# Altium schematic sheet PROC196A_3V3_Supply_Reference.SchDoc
size 431 x 279 mm; Date: Not shown in title block; ApprovedBy: Not shown in title block; CheckedBy: Not shown in title block; Author: Not shown in title block; CompanyName: Not shown in title block; Engineer: Not shown in title block; Organization: Not shown in title block; Address1: Not shown in title block; Address2: Not shown in title block; Address3: Not shown in title block; Address4: Not shown in title block; DocumentNumber: 7; Revision: Use project parameter SCH_Rev; SheetNumber: 7; SheetTotal: 25; PageSetup: Record=PageOptions¦CenterHorizontal=True¦CenterVertical=True¦PrintScale=1.00¦XCorrection=1.00¦YCorrection=1.00¦PrintKind=0¦BorderSize=5000000¦LeftOffset=0¦BottomOffset=0¦Orientation=2¦PaperLength=1000¦PaperWidth=1000¦Scale=100¦PaperSource=15¦PrintQuality=600¦MediaType=1¦DitherType=10¦PaperKind=Letter¦PrintScaleMode=1
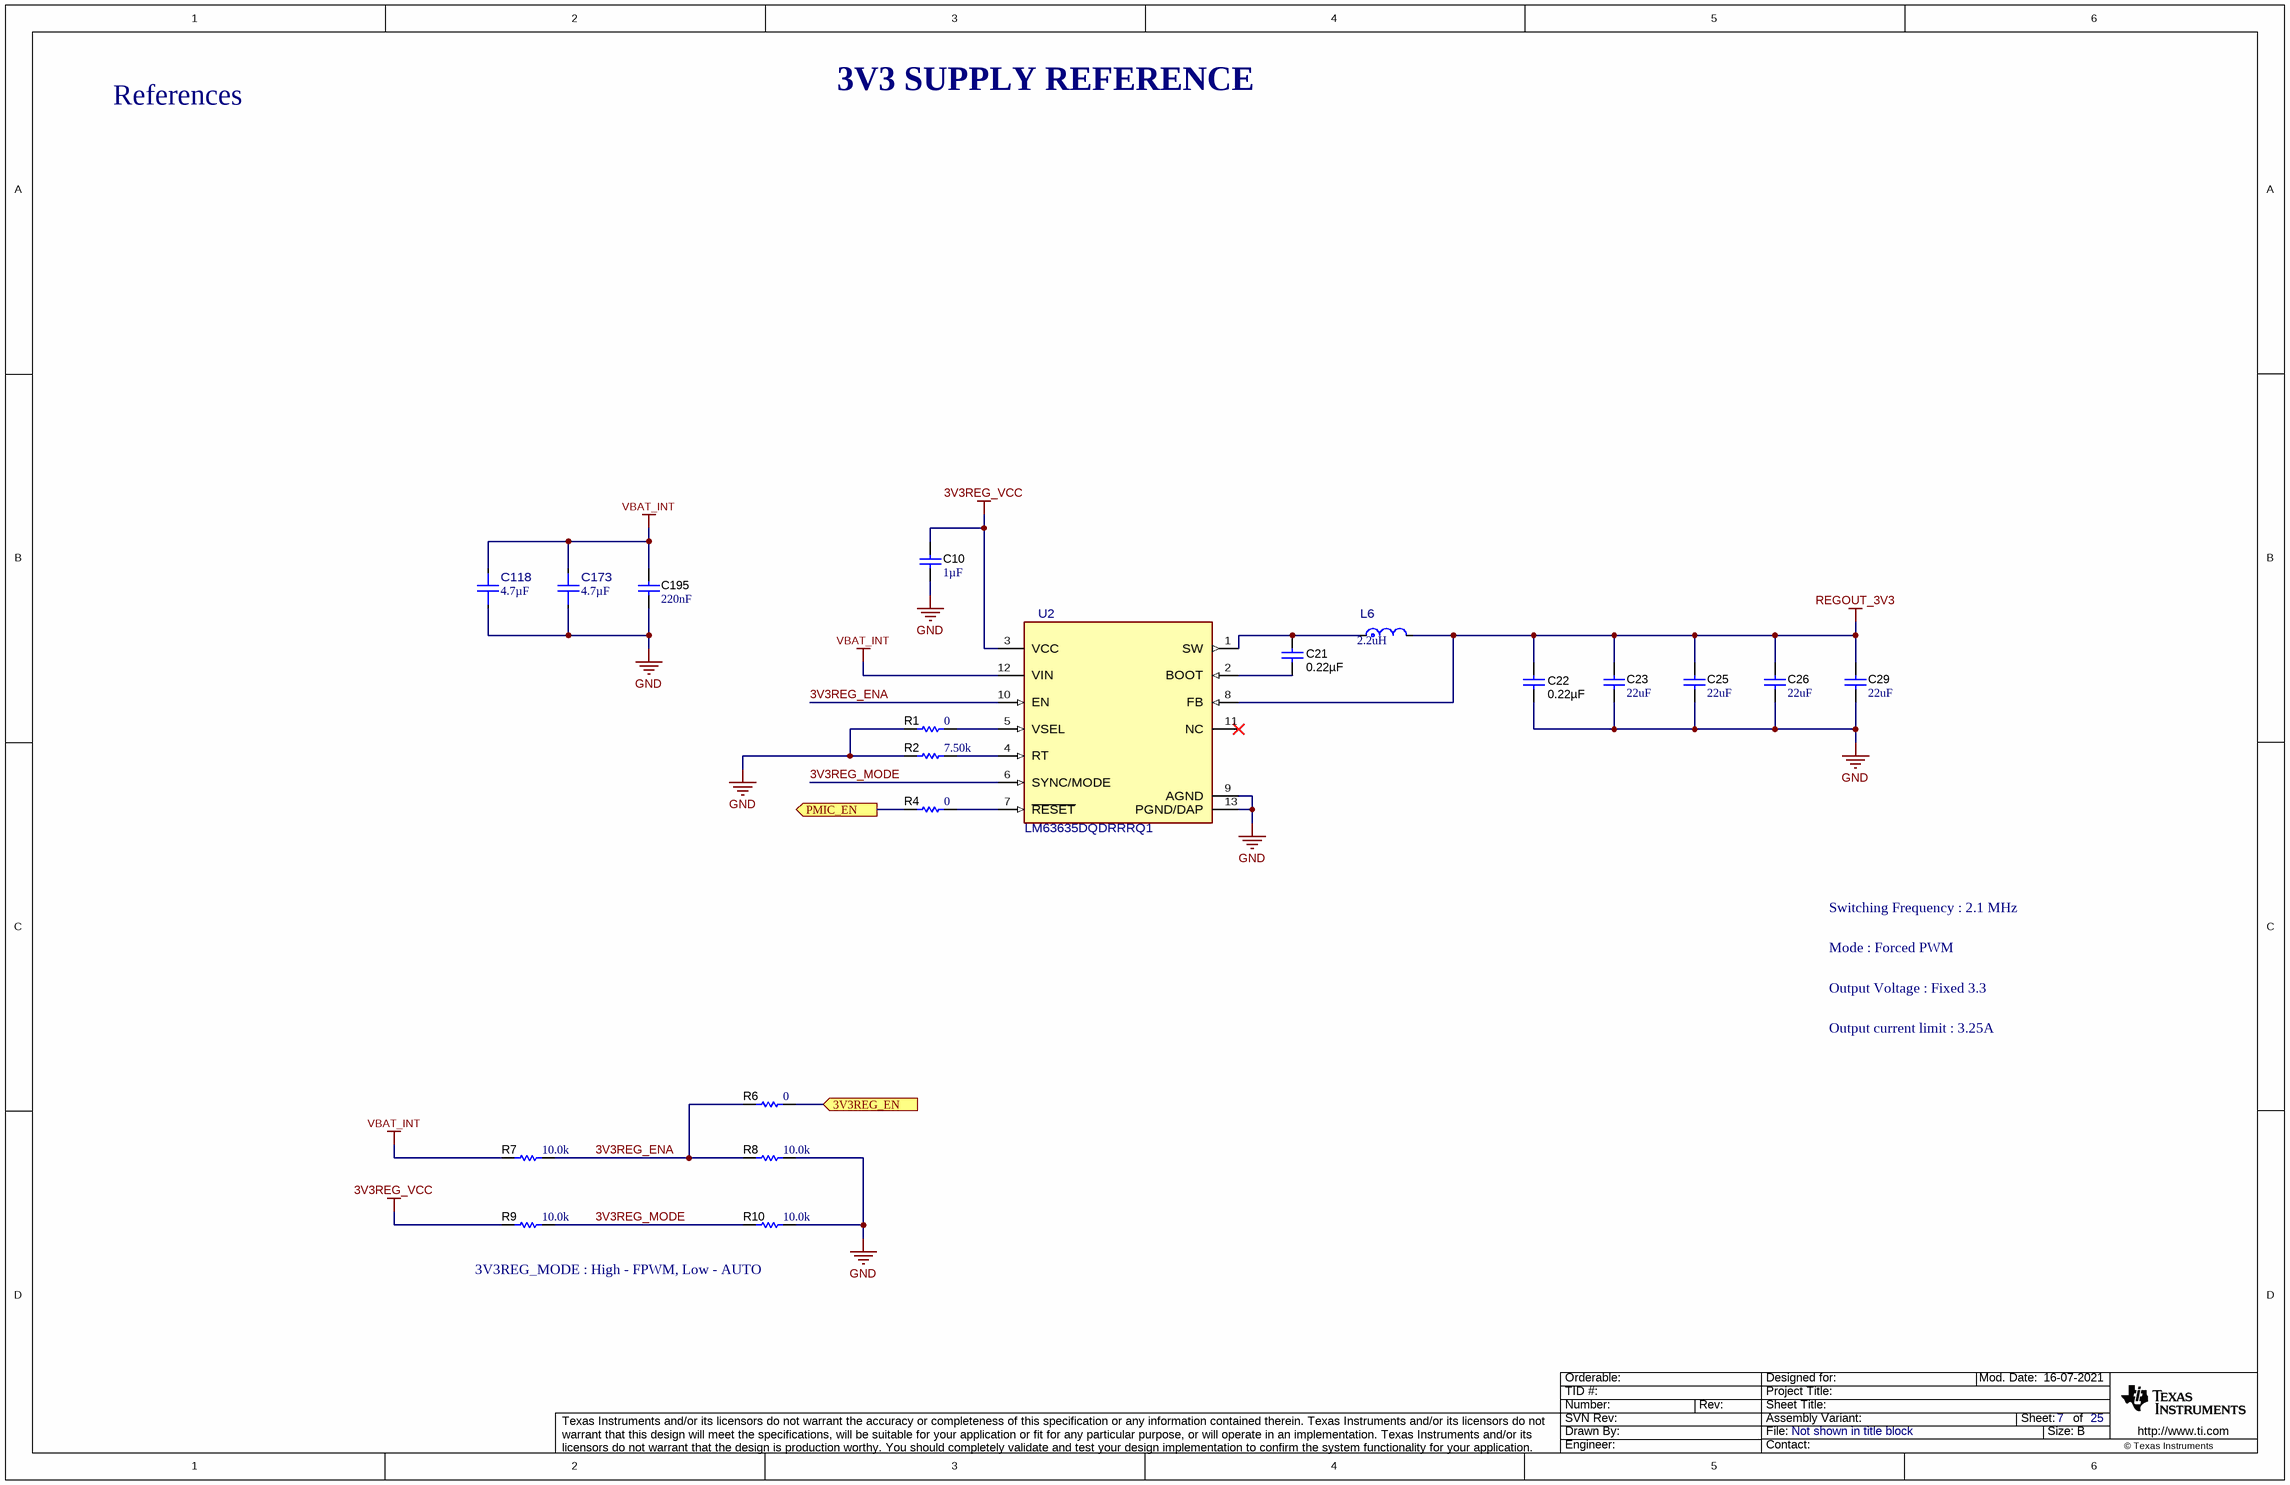
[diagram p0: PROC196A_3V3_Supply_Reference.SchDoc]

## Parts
C10  Cap_F: 1µF  [0603L]  (hidden comment: GCM188R71C105KA64D)
C21  ValueDisplayed: 0.22µF  [0402L]  (hidden comment: GCM155R71C224KE02D)
C22  ValueDisplayed: 0.22µF  [0402L]  (hidden comment: GCM155R71C224KE02D)
C23  ValueDisplayed: 22uF  [1206_180L]  (hidden comment: GCM31CR71A226KE02L)
C25  ValueDisplayed: 22uF  [1206_180L]  (hidden comment: GCM31CR71A226KE02L)
C26  ValueDisplayed: 22uF  [1206_180L]  (hidden comment: GCM31CR71A226KE02L)
C29  ValueDisplayed: 22uF  [1206_180L]  (hidden comment: GCM31CR71A226KE02L)
C118  Cap_F: 4.7µF  [FP-CGA4J1X7R1H475K125AC_0805-MFG]  (hidden comment: CGA4J1X7R1H475K125AC)
C173  Cap_F: 4.7µF  [FP-CGA4J1X7R1H475K125AC_0805-MFG]  (hidden comment: CGA4J1X7R1H475K125AC)
C195  Cap_F: 220nF  [0603L]  (hidden comment: CGA3E3X7R1H224K080AB)
L6  value 2.2uH  [FP-XEL4030-222MEC_SMT2_4MM0_4MM0-MFG]  (hidden comment: XEL4030-222MEC)
R1  ValueDisplayed: 0  [0402L]  (hidden comment: ERJ-2GE0R00X)
R2  ValueDisplayed: 7.50k  [0402L]  (hidden comment: CRCW04027K50FKED)
R4  ValueDisplayed: 0  [0402L]  (hidden comment: ERJ-2GE0R00X)
R6  ValueDisplayed: 0  [0402L]  (hidden comment: ERJ-2GE0R00X)
R7  ValueDisplayed: 10.0k  [0402L]  (hidden comment: CRCW040210K0FKED)
R8  ValueDisplayed: 10.0k  [0402L]  (hidden comment: CRCW040210K0FKED)
R9  ValueDisplayed: 10.0k  [0402L]  (hidden comment: CRCW040210K0FKED)
R10  ValueDisplayed: 10.0k  [0402L]  (hidden comment: CRCW040210K0FKED)
U2  LM63635DQDRRRQ1  [DRR0012E-MFG]

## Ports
3V3REG_EN (in), PMIC_EN (out)

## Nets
3V3REG_VCC: C10.1 R9.2 U2.3(VCC)
GND: C10.2 C22.1 C23.2 C25.2 C26.2 C29.2 C118.1 C173.1 C195.2 R1.2 R2.1 R8.2 R10.1 U2.9(AGND) U2.13(PGND/DAP)
REGOUT_3V3: C22.2 C23.1 C25.1 C26.1 C29.1 L6.2 U2.8(FB)
VBAT_INT: C118.2 C173.2 C195.1 R7.1 U2.12(VIN)
3V3REG_EN: R6.2 ; port 3V3REG_EN
3V3REG_ENA: R6.1 R7.2 R8.1 U2.10(EN)
3V3REG_MODE: R9.1 R10.2 U2.6(SYNC/MODE)
PMIC_EN: R4.1 ; port PMIC_EN
NetC21_1: C21.1 U2.2(BOOT)
NetC21_2: C21.2 L6.1 U2.1(SW)
NetR1_1: R1.1 U2.5(VSEL)
NetR2_2: R2.2 U2.4(RT)
NetR4_2: R4.2 U2.7(~{RESET})

Not connected (* = marked no-connect by the designer): U2 11(NC)*

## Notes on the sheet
- 3V3 SUPPLY REFERENCE
- References
- Switching Frequency : 2.1 MHz
- Mode : Forced PWM
- Output Voltage : Fixed 3.3
- Output current limit : 3.25A
- 3V3REG_MODE : High - FPWM, Low - AUTO

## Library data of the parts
C10 = CMP-0007136-5: CAP, CERM, 1 uF, 16 V, +/- 10%, X7R, AEC-Q200 Grade 1, 0603; Manufacturer: MuRata; TaMin_C: -55°C; Polarized: N; SizeAreaWB_mm2: 4.68; Value1: Unknown; U/M: EA; Value: 1uF; TaMax_C: 125°C; SizeZ_mm: 1; SizeX_mm: 1.6; SizeY_mm: 0.8; Cap_Case: 0603; Value2: 16V; SizeArea_mm2: 1.28; AEC Qualified: Y; AEC Category: Q200
C21 C22 = CMP-0078265-1: CAP, CERM, 0.22 µF, 16 V,+/- 10%, X7R, AEC-Q200 Grade 1, 0402; Manufacturer: MuRata; TaMin_C: -55°C; Polarized: N; SizeAreaWB_mm2: 3; U/M: EA; Value: 0.22uF; TaMax_C: 125°C; SizeZ_mm: 0.6; SizeX_mm: 1; SizeY_mm: 0.5; Cap_Case: 0402; Value2: 16V; CompType: Capacitor; AEC Qualified: Y; Cap_F: 220nF; AEC Category: Q200
C23 C25 C26 C29 = CMP-0008811-3: CAP, CERM, 22 uF, 10 V, +/- 10%, X7R, AEC-Q200 Grade 1, 1206; Manufacturer: MuRata; SizeX_mm: 3.2; SizeArea_mm2: 5.12; Polarized: N; SizeY_mm: 1.6; Value2: 10V; TaMin_C: -55°C; SizeZ_mm: 1.8; Cap_Case: 1206; AEC Grade: 1; Value1: Unknown; U/M: EA; AEC Qualified: Y; SizeAreaWB_mm2: 10.92; AEC Category: Q200; Value: 22uF; Cap_F: 22µF; TaMax_C: 125°C
C118 C173 = CMP-0090082-1: Cap Ceramic 4.7uF 50V X7R 10% Pad SMD 0805 +125°C Automotive T/R; Manufacturer: TDK Corporation; SizeZ_mm: 1.45mm; Tolerance_%: 0.1%; AEC Qualified: Yes; TempCo: 15%; AEC Grade: Grade 1; Value: 4.7µF
C195 = CMP-0007094-5: CAP, CERM, 0.22 uF, 50 V, +/- 10%, X7R, AEC-Q200 Grade 1, 0603; Manufacturer: TDK; TaMin_C: -55°C; ESR_ohm: 0.021699; Polarized: N; SizeAreaWB_mm2: 4.68; Value1: 0.021699 ohm; U/M: EA; Value: 0.22uF; TaMax_C: 125°C; SizeZ_mm: 1; SizeX_mm: 1.6; SizeY_mm: 0.8; Cap_Case: 0603; Value2: 50V; SizeArea_mm2: 1.28; AEC Qualified: Y; IRMS_A: 1.12496A; AEC Category: Q200
L6 = CMP-0120010-1: Ultra-Low Loss Shielded Power Inductors 2.2µH ±20% 7.8A 22.1mOhms; Manufacturer: Coilcraft; AEC Grade: Grade 1; AEC Qualified: Yes; DCR_ohm: 22.1m; Isat: 6.1A; Material: Composite; SizeZ_mm: 3.1mm; Self Resonant Frequency: 40MHz; Shrouded: true; TaMax_C: +125°C; TaMin_C: -40°C; Test Frequency: 1MHz
R1 R4 R6 = CMP-0026992-3: RES, 0, 5%, 0.1 W, AEC-Q200 Grade 0, 0402; Manufacturer: Panasonic; Power_W: 100mW; TempCo: 600 ppm/C; Value_Code: 0000; Value: 0; EIA_Code: E24; SizeX_mm: 1; SizeY_mm: 0.5; SizeZ_mm: 0.6; Value2: 0.1W; CompType: Resistor; AEC Qualified: Y; VDC_V: 50V; AEC Category: Q200; SizeAreaWB_mm2: 3; INSTALLATION: DNP
R2 = CMP-0026555-2: RES, 7.50 k, 1%, 0.063 W, AEC-Q200 Grade 0, 0402; Manufacturer: Vishay-Dale; Power_W: 63mW; TempCo: 100 ppm/C; Value_Code: 7k50; Value: 7.50k; EIA_Code: E96; Res_ohm: 7.5k; SizeX_mm: 1; SizeY_mm: 0.5; SizeZ_mm: 0.6; Value2: 0.063W; AEC Qualified: Y; VDC_V: 50V; AEC Category: Q200; AEC Grade: 0
R7-R10 = CMP-0025958-3: RES, 10.0 k, 1%, 0.063 W, AEC-Q200 Grade 0, 0402; Manufacturer: Vishay-Dale; Power_W: 63mW; TempCo: 100 ppm/C; Value_Code: 10k0; Value: 10.0k; EIA_Code: E96; Res_ohm: 10k; SizeX_mm: 1; SizeY_mm: 0.5; SizeZ_mm: 0.6; Value2: 0.063W; AEC Qualified: Y; VDC_V: 50V; AEC Category: Q200; AEC Grade: 0
U2 = CMP-0088353-1: 3.5-V to 36-V, 1.5-A, and 2.5-A Automotive Step-down Voltage Converter; Manufacturer: Texas Instruments; Max Supply Voltage: 32V; Number Of Outputs: 1; Standoff Height: 0mm; Output Type: Fixed,AdjustableProgrammable; Switching Topology: Buck; TaMax_C: +125°C; Min Supply Voltage: 3.5V; Max Duty Cycle: 98%; TaMin_C: -40°C; AEC Qualified: Yes; Output Voltage: 3.3/5/1-20V; AEC Grade: Grade 1; TJmax_C: +150°C; Nominal Supply Current: 23uA; SizeZ_mm: 0.8mm; Switching Frequency: 400/2100/250-2200kHz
